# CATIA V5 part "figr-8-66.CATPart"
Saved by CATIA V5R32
Part number: Part1
Bounding box of the stored display mesh (mm): x -53.439 to 53.439, y -63.41 to 63.41, z -17.5 to 17.5
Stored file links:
  D:\PROJECTS\Project 2022\CATIA V5 6R 2022\Resources\Part Files\c08_catia_v5_6r2022_prt\figr-8-66.CATPart
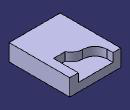
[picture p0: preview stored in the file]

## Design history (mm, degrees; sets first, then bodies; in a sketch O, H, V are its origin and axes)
Body1 (main body)
  Sketch1 on xy-plane, origin (0, 0, 0), H (1, 0, 0), V (0, 1, 0)
    line L1 (-53.4395, 63.4095) -> (53.4395, 63.4095)
    line L2 (53.4395, 63.4095) -> (53.4395, -63.4095)
    line L3 (53.4395, -63.4095) -> (-53.4395, -63.4095)
    line L4 (-53.4395, -63.4095) -> (-53.4395, 63.4095)
    axis line L5 (53.4395, -63.4095) -> (-53.4395, 63.4095)
    horizontal: L1 H, L3 H
    vertical: L2 V, L4 V
    midpoint: O L5
  Pad1: profile Sketch1, direction (0, 0, 1), length 17.5, mirrored extent
  Body2
    Sketch2 on xy-plane, origin (0, 0, 0), H (1, 0, 0), V (0, 1, 0)
      line L1 (-36.9238, 103.6333) -> (-36.9238, 51.4035)
      arc A1 centre (-11.4307, 51.4035) radius 25.4931 from (-36.9238, 51.4035) to (-11.4307, 25.9104) ccw
      arc A2 centre (-11.4307, 0.4172) radius 25.4931 from (-11.4307, 25.9104) to (11.4981, 11.5602) cw
      line L2 (11.4981, 11.5602) -> (35.6176, 11.5602)
      line L3 (35.6176, 11.5602) -> (35.6176, 103.6333)
      line L4 (35.6176, 103.6333) -> (-36.9238, 103.6333)
      vertical: L1 V, L3 V
      tangency: A1 L1, A2 L1, A2 A1
      horizontal: L2 H, L4 H
    Pad2: profile Sketch2, direction (0, 0, 1), length 34.5
  Remove1: tool Body2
